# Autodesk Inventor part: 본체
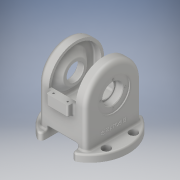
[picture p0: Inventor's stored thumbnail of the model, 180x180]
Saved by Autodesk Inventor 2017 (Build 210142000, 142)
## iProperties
Part Number: 본체
Material: 알루미늄 6061
Document SubType Name: Modeling
Designer: MRC
Density: 2.7 g/cm^3
Appearance: 알루미늄 - 평지
Mass: 1199.24 g
Surface Area: 1051.77 cm^2
Volume: 444.164 cm^3
Author: MRC
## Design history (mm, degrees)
sketch "스케치1"
  geometry: C1 r 71 at (0, 0); 1 further point
  constraints: 1 centre point, 1 coincident
  dimensions: "d0" = 142 diameter of C1
extrude "돌출1" new body sketch "스케치1" distance "d1" = 13; taper "d2" = 0 deg
sketch "스케치2"
  geometry: L1 (-44, 51)-(44, 51); L2 (44, 51)-(44, -51); L3 (44, -51)-(-44, -51); L4 (-44, -51)-(-44, 51); L5 (-44, 51)-(44, -51); L6 (44, 51)-(-44, -51); 1 further point
  constraints: 12 end point, 2 midpoint, 2 parallel, 1 horizontal, 1 perpendicular
  dimensions: "d3" = 88 distance of L2.end L3.end; "d4" = 102 distance of L1.end L2.end
extrude "돌출2" join sketch "스케치2" distance "d5" = 68; taper "d6" = 0 deg
sketch "스케치3"
  geometry: L1 (81, -51)-(81, 51) reference; C1 r 51 at (81, 0); 1 further point
  constraints: 1 centre point, 1 midpoint
  dimensions: "d7" = 102 diameter of C1
extrude "돌출3" join sketch "스케치3" stored distance "d8" = 88; taper "d9" = 0 deg
sketch "스케치5"
  geometry: L1 (71, 13)-(-71, 13) reference; L2 (-71, 0)-(71, 0) reference; L3 (-28, 19)-(28, 19); L4 (28, 19)-(28, 0); L5 (28, 0)-(-28, 0); L6 (-28, 0)-(-28, 19); 2 further points
  constraints: 8 end point, 2 midpoint, 2 parallel, 1 horizontal, 1 perpendicular, 1 point on line
  dimensions: "d10" = 56 distance of L3.start L3.end; "d11" = 19 distance of L3.end L4.end
extrude "돌출4" cut sketch "스케치5" stored distance "d12" = 142; taper "d13" = 0 deg
sketch "스케치6"
  geometry: L1 (28, -51)-(-28, -51) reference; L2 (28, -51)-(28, 51) reference; L3 (-28, 51)-(28, 51) reference; L4 (-28, 51)-(-28, -51) reference; C1 r 14 at (0, 0); 1 further point
  constraints: 1 centre point, 1 coincident
  dimensions: "d15" = 28 diameter of C1
extrude "돌출5" cut sketch "스케치6" distance "d16" = 37; taper "d17" = 0 deg
sketch "스케치7"
  geometry: C1 r 30 at (0, 0); 1 further point
  constraints: 1 centre point, 1 coincident
  dimensions: "d18" = 60 diameter of C1
extrude "돌출6" cut sketch "스케치7" distance "d19" = 22; taper "d20" = 0 deg
sketch "스케치8"
  geometry: L1 (16, -62)-(16, -68) reference; L2 (0, -68)-(16, -68) reference; L3 (0, -68)-(0, 0) reference; L4 (88, 0)-(0, 0) reference; L5 (88, -68)-(88, 0) reference; L6 (72, -68)-(88, -68) reference; L7 (72, -68)-(72, -62) reference; L8 (72, -62)-(16, -62) reference; L9 (24, 0)-(64, 0); L10 (64, 0)-(64, -20); L11 (64, -20)-(24, -20); L12 (24, -20)-(24, 0); 2 further points
  constraints: 8 end point, 2 midpoint, 2 parallel, 1 horizontal, 1 perpendicular, 1 point on line
  dimensions: "d21" = 40 distance of L10.end L11.end; "d22" = 20 distance of L9.end L10.end
extrude "돌출7" join sketch "스케치8" distance "d23" = 10; taper "d24" = 0 deg
sketch "스케치10"
  geometry: L1 (-39, 81)-(39, 81); L2 (39, 81)-(39, 40); L3 (39, 40)-(-39, 40); L4 (-39, 40)-(-39, 81); L5 (-44, 13)-(-44, 81) reference; L6 (44, 13)-(44, 81) reference; 2 further points
  constraints: 8 end point, 2 parallel, 1 horizontal, 1 horizontal alignment, 1 midpoint, 1 perpendicular
  dimensions: "d25" = 40 distance from line of point (0, 0) L3; "d26" = 5 distance between parallel lines of L5 L4; "d27" = 5 distance between parallel lines of L6 L2
extrude "돌출8" cut sketch "스케치10" stored distance "d28" = 92; taper "d29" = 0 deg
sketch "스케치11"
  geometry: L1 (-44, 81)-(-20, 81) reference; L2 (-20, 81)-(20, 81) reference; L3 (20, 81)-(44, 81) reference; L4 (44, 81)-(44, 81) reference; L5 (44, 81)-(20, 81) reference; L6 (20, 81)-(-20, 81) reference; L7 (-20, 81)-(-44, 81) reference; L8 (-44, 81)-(-44, 81) reference; L9 (-25, 132)-(25, 132); L10 (25, 132)-(25, 81); L11 (25, 81)-(-25, 81); L12 (-25, 81)-(-25, 132); 2 further points
  constraints: 8 end point, 2 midpoint, 2 parallel, 1 horizontal, 1 perpendicular, 1 point on line
  dimensions: "d30" = 50 distance of L9.start L9.end; "d31" = 51 distance of L9.end L10.end
extrude "돌출9" cut sketch "스케치11" stored distance "d32" = 102; taper "d33" = 0 deg
sketch "스케치13"
  geometry: L1 (46, 0)-(-46, 0) reference; L2 (-46, 0)-(46, 0); A1 r 51 centre (0, 0) between (51, 0) and (-51, 0) reference; A2 r 46 centre (0, 0) between (46, 0) and (-46, 0); 1 further point
  constraints: 2 end point, 2 point on circle, 1 centre point, 1 coincident, 1 collinear
extrude "돌출11" cut sketch "스케치13" distance "d40" = 14; taper "d41" = 0 deg
sketch "스케치15"
  geometry: L1 (-25, 81)-(25, 81) reference; L2 (25, 81)-(39, 81) reference; L3 (-39, 81)-(-55.824, 81); L4 (39, 81)-(50.959, 81); L5 (44, 81)-(25, 81) reference; L6 (-39, 127)-(-39, 81) reference; L7 (-39, 81)-(-39, 114.5); L8 (-39, 114.5)-(-27, 102.5); L9 (-39, 81)-(-27, 81); L10 (-27, 102.5)-(-27, 81); L11 (-39, 81)-(-25, 81) reference; 1 further point
  constraints: 12 end point, 2 point on line, 1 collinear, 1 horizontal, 1 perpendicular
  dimensions: "d42" = 67 diameter of L7.end L9; "d43" = 135 deg angle of L8 L6; "d44" = 12 distance between parallel lines of L6 L10
revolve "회전1" sketch "스케치15" stored, may be unused: angle "d45" = 90 deg
sketch "스케치16"
  geometry: C1 r 30 at (51, 68); A1 r 51 centre (51, 68) between (102, 68) and (0, 68) reference; 1 further point
  constraints: 1 centre point, 1 coincident
  dimensions: "d46" = 60 diameter of C1
extrude "돌출12" cut sketch "스케치16" distance "d47" = 2; taper "d48" = 0 deg
sketch "스케치17"
  geometry: C1 r 30 at (0, 0) reference; C2 r 18.5 at (0, 0); 1 further point
  constraints: 1 centre point, 1 coincident
  dimensions: "d49" = 37 diameter of C2
extrude "돌출13" cut sketch "스케치17" distance "d50" = 13; taper "d51" = 0 deg
sketch "스케치18"
  geometry: C1 r 21.5 at (0, 0) reference; C2 r 16 at (0, 0); 1 further point
  constraints: 1 centre point, 1 coincident
  dimensions: "d52" = 32 diameter of C2
extrude "돌출14" cut sketch "스케치18" stored distance "d53" = 32 (= d52); taper "d54" = 0 deg
sketch "스케치19"
  geometry: C1 r 14 at (0, 0) reference; C2 r 11 at (0, 0); 1 further point
  constraints: 1 centre point, 1 coincident
  dimensions: "d55" = 22 diameter of C2
extrude "돌출15" cut sketch "스케치19" stored distance "d56" = 13; taper "d57" = 0 deg
sketch "스케치20"
  geometry: L1 (-28, -10.77)-(-28, -65.246) reference; L2 (-28, 65.246)-(-28, 10.77) reference; L3 (28, 10.77)-(28, 65.246) reference; L4 (28, -65.246)-(28, -10.77) reference; L5 (-55, -25)-(55, -25); L6 (55, -25)-(55, 25); L7 (55, 25)-(-55, 25); L8 (-55, 25)-(-55, -25); L9 (-55, -25)-(55, 25); L10 (55, -25)-(-55, 25); A1 r 30 centre (0, 0) between (-28, 10.77) and (-28, -10.77) reference; A2 r 71 centre (0, 0) between (-28, 65.246) and (-28, -65.246) reference; A3 r 30 centre (0, 0) between (28, -10.77) and (28, 10.77) reference; A4 r 71 centre (0, 0) between (28, -65.246) and (28, 65.246) reference; 5 further points
  constraints: 12 end point, 4 coincident, 2 midpoint, 2 parallel, 1 horizontal, 1 perpendicular
  dimensions: "d58" = 110 distance of L7.end L6.end; "d59" = 50 distance of L6.end L5.end
hole "구멍1" sketch "스케치20" at (-55, 25), (-55, -25), (55, -25), (55, 25) diameter "d60" = 9; stored, may be unused: countersink angle "d64" = 90 deg, drill point angle "d66" = 118 deg; dims "d61" = 6, "d62" = 15, "d63" = 8.8, "d65" = 13
sketch "스케치21" dims "d67" = 46
  geometry: C1 r 14 at (0, 0) reference; 3 further points
  constraints: 2 vertical alignment, 1 coincident, 2 other
hole "구멍2" sketch "스케치21" at (0, 23) diameter "d68" = 3.242; stored, may be unused: countersink angle "d72" = 90 deg, drill point angle "d74" = 118 deg; dims "d69" = 8, "d70" = 15, "d71" = 8.8, "d73" = 10
sketch "스케치22" dims "d78" = 46
  geometry: C1 r 30 at (0, 0) reference; 3 further points
  constraints: 2 vertical alignment, 1 coincident, 2 other
hole "구멍3" sketch "스케치22" at (0, 23) diameter "d79" = 3.242; stored, may be unused: countersink angle "d83" = 90 deg, drill point angle "d85" = 118 deg; dims "d80" = 8, "d81" = 15, "d82" = 8.8, "d84" = 10
sketch "스케치23"
  geometry: L1 (7, 7)-(33, 7); L2 (33, 7)-(33, 115); L3 (33, 115)-(7, 115); L4 (7, 115)-(7, 7); L5 (7, 7)-(33, 115); L6 (33, 7)-(7, 115); 5 further points
  constraints: 12 end point, 4 coincident, 2 midpoint, 2 parallel, 1 horizontal, 1 perpendicular
  dimensions: "d89" = 26 distance of L3.end L2.end; "d90" = 108 distance of L2.end L1.end
hole "구멍4" sketch "스케치23" at (7, 115), (33, 115), (33, 7), (7, 7) diameter "d91" = 3.242; stored, may be unused: countersink angle "d95" = 90 deg, drill point angle "d97" = 118 deg; dims "d92" = 8, "d93" = 15, "d94" = 8.8, "d96" = 10
fillet "모깎기1" dims "d98" = 0.3
fillet "모깎기2" dims "d99" = 8
fillet "모깎기3" dims "d100" = 6
fillet "모깎기4" dims "d101" = 3
fillet "모깎기5" dims "d102" = 3
fillet "모깎기6" dims "d103" = 3
fillet "모깎기7" dims "d104" = 3
fillet "모깎기8" dims "d105" = 3
chamfer "모따기1" distance "d106" = 1; stored, may be unused: second distance "d107" = 2, angle "d108" = 45 deg
fillet "모깎기9" dims "d109" = 3
fillet "모깎기10" dims "d110" = 3
fillet "모깎기11" dims "d111" = 3
fillet "모깎기12" dims "d112" = 3
sketch "스케치24"
  geometry: L1 (-60.512, -81)-(60.512, -81) reference; 3 further points
  constraints: 1 midpoint, 1 vertical alignment, 1 other
  dimensions: "d113" = 30 distance from line of L1 point (0, -51)
feature "엠보싱1" sketch "스케치24" dims "d114" = 0.5, "d115" = 0
node "솔리드1"
mirror "미러1"
mirror "미러2"
mirror "미러3"
mirror "미러4"
pattern_circular "원형 패턴1" dims angle "d76" = 360 deg
pattern_circular "원형 패턴2" dims angle "d87" = 360 deg
mirror "미러5"
node "투영된 루프1"
node "투영된 루프2"
node "투영된 루프3"
node "투영된 루프4"
node "투영된 루프6"
node "투영된 루프7"
node "투영된 루프8"
node "투영된 루프9"
node "투영된 루프10"
